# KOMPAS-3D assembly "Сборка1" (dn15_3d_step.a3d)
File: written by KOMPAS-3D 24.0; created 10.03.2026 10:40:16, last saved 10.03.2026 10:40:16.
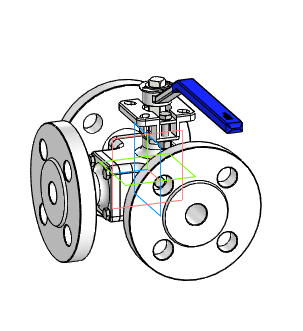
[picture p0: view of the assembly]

Document properties: Автор: R2D2; Полное имя файла: C:\Users\R2D2\Downloads\dn15_3d_step.a3d

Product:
- Component [detail]: Деталь  | qty 1  | Автор: R2D2; source file: Деталь Деталь.m3d
- Component [detail]: Деталь1  | qty 1  | Автор: R2D2; source file: Деталь1 Деталь1.m3d
- Component [detail]: AS 1110 - M4 x 8  | qty 1  | Автор: R2D2; source file: AS 1110 - M4 x 8 AS 1110 - M4 x 8.m3d
- Component [detail]: AS 1110 - M4 x 8  | qty 11  | Комментарий: Болты и винты   шестигранные точные   метрические ISO; Автор: R2D2; additional columns: Сталь, мягкая; source file: AS 1110 - M4 x 8 AS 1110 - M4 x 8.m3d
- Component [detail]: AS 1110 - M5 x 20  | qty 1  | Автор: R2D2; source file: AS 1110 - M5 x 20 AS 1110 - M5 x 20.m3d
- Component [detail]: AS 1110 - M5 x 20  | qty 1  | Комментарий: Болты и винты   шестигранные точные   метрические ISO; Автор: R2D2; additional columns: Сталь, мягкая; source file: AS 1110 - M5 x 20 AS 1110 - M5 x 20.m3d
- Component [detail]: ANSI B18.2.4.2M - M5x0,8 - 8  | designation ANSI B18.2.4.2M - M5x0,8  | qty 1  | Автор: R2D2; source file: ANSI B18.2.4.2M - M5x0,8 ANSI B18.2.4.2M - M5x0,8 - 8.m3d
- Component [detail]: ANSI B18.2.4.2M - M5x0,8 - 8  | designation ANSI B18.2.4.2M - M5x0,8  | qty 1  | Комментарий: Типы метрических   шестигранных гаек   2; Автор: R2D2; additional columns: Сталь, мягкая; source file: ANSI B18.2.4.2M - M5x0,8 ANSI B18.2.4.2M - M5x0,8 - 8.m3d
- Part/product: Сборка1

Referenced files in C:\Users\R2D2\Downloads\: Деталь Деталь.m3d, Деталь1 Деталь1.m3d, AS 1110 - M4 x 8 AS 1110 - M4 x 8.m3d, AS 1110 - M5 x 20 AS 1110 - M5 x 20.m3d, ANSI B18.2.4.2M - M5x0,8 ANSI B18.2.4.2M - M5x0,8 - 8.m3d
